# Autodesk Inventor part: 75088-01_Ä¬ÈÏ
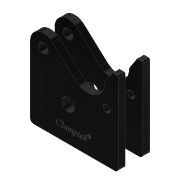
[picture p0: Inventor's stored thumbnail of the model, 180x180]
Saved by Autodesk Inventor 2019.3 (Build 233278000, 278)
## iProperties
Created: 2010-06
Part Number: 75088-01_Ä¬ÈÏ
Material: Ogólny
Document SubType Name: Modeling
Designer: CADENGINEERING4
Density: 1 g/cm^3
Appearance: Gładki — czarny
Author: CADENGINEERING4
Revision Number: ÈÎºÎ
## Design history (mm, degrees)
feature "NONE"
feature "NONE:1"
node "Bryła1"
node "Bryła2"
